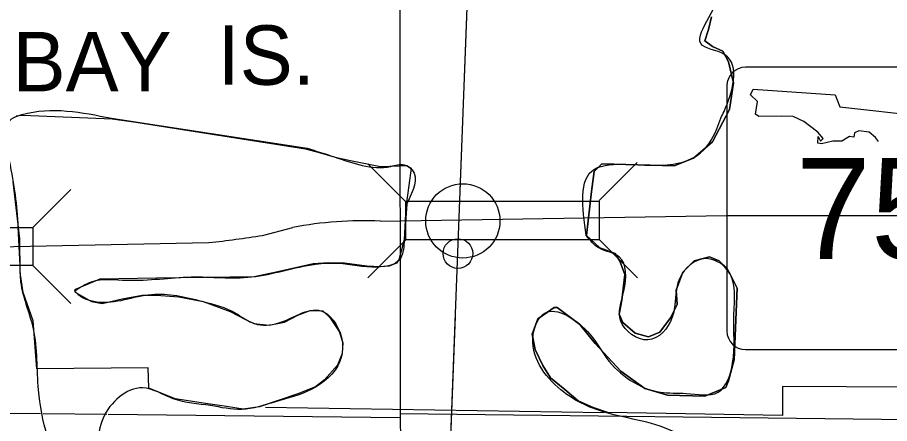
# Model space of a CAD drawing. Extents: x 408847 to 817539, y 923858 to 1151780.
# Drawn here: x 476052 to 481921, y 1078190 to 1080923 of the extents above; entities that cross this region are included whole.
import ezdxf

# ---------------------------------------------------------------- set-up
doc = ezdxf.new("R2010")
doc.units = 0
for name, color, linetype in [('Bridges', 7, 'Continuous'), ('Cities Incorporated Area', 7, 'Continuous'), ('Cities Incorporated Linear Boundaries', 7, 'Continuous'), ('Lakes and Ponds', 7, 'Continuous'), ('Level 12', 7, 'Continuous'), ('Level 39', 7, 'Continuous'), ('Narrow River Creek and Branch and Slough', 7, 'Continuous'), ('Roadshields State Highways', 7, 'Continuous'), ('Section Lines', 7, 'Continuous'), ('State Routes Highway Center Lines', 7, 'Continuous'), ('Township  and Range lines', 7, 'Continuous')]:
    doc.layers.add(name, color=color, linetype=linetype)

msp = doc.modelspace()

# ---------------------------------------------------------------- linework, layer by layer
at = {"layer": 'Bridges'}
for p, q in [((478409.7, 1079938), (478665.7, 1079682)), ((479966.8, 1079691.1), (480222.8, 1079947.1)), ((476155.3, 1079509.6), (476411.3, 1079765.6)), ((478665.7, 1079426), (478665.7, 1079687.3)), ((478665.7, 1079687.3), (479967.5, 1079687.3)), ((479967.5, 1079687.3), (479967.5, 1079426)), ((478665.7, 1079426), (478409.7, 1079170)), ((479967.5, 1079426), (478665.7, 1079426)), ((479969.8, 1079426), (480225.8, 1079170)), ((476155.3, 1079253.6), (476411.3, 1078997.6))]:
    msp.add_line(p, q, dxfattribs=at)
msp.add_lwpolyline([(475643.3, 1079509.6), (476155.3, 1079509.6), (476155.3, 1079253.6), (475643.3, 1079253.6)], close=True, dxfattribs=at)
msp.add_circle((479049.7, 1079554), 250, dxfattribs=at)
at = {"layer": 'Cities Incorporated Area'}
for p, q in [((486536.7, 1078406.2), (481199.8, 1078440.5)), ((481199.8, 1078440.5), (481201.8, 1078244.7)), ((481201.8, 1078244.7), (480026.3, 1078263.9))]:
    msp.add_line(p, q, dxfattribs=at)
for points in [[(480139.1, 1079193.4), (480107, 1079283.3), (480074.9, 1079334.6), (479972.3, 1079373.1), (479882.5, 1079456.6), (479914.6, 1079751.8), (479933.8, 1079886.6), (479985.2, 1079937.9), (480472.6, 1079925.1), (480600.9, 1079976.4), (480729.2, 1080085.5), (480844.6, 1080303.8), (480870.3, 1080483.5), (480838.2, 1080624.7), (480799.7, 1080695.3), (480729.2, 1080727.4), (480677.8, 1080765.9), (480703.5, 1080842.9), (480722.7, 1080926.3)], [(480722.7, 1080926.3), (480703.5, 1080842.9), (480677.8, 1080765.9), (480729.2, 1080727.4), (480799.7, 1080695.3), (480838.2, 1080624.7), (480870.3, 1080483.5), (480844.6, 1080303.8), (480729.2, 1080085.5), (480600.9, 1079976.4), (480472.6, 1079925.1), (479985.2, 1079937.9), (479933.8, 1079886.6), (479914.6, 1079751.8), (479882.5, 1079456.6), (479972.3, 1079373.1), (480074.9, 1079334.6), (480107, 1079283.3), (480139.1, 1079193.4)], [(476043.5, 1080261.4), (476087.1, 1080265.4), (476690.1, 1080241.5), (476848.8, 1080217.7), (477991.4, 1080039.1), (478082.6, 1080015.2), (478189.8, 1079983.5), (478292.9, 1079959.7), (478495.2, 1079920), (478622.2, 1079923.9), (478673.8, 1079927.9), (478701.5, 1079908.1), (478685.7, 1079792.9), (478665.8, 1079646), (478653.9, 1079427.7), (478618.2, 1079292.7), (478602.3, 1079268.9), (478554.7, 1079249), (478495.2, 1079245.1), (478404, 1079249), (478253.2, 1079268.9), (478146.1, 1079272.9), (478043, 1079264.9), (477793, 1079209.3), (477646.2, 1079177.6), (476987.7, 1079169.6), (476606.8, 1079161.7), (476436.2, 1079090.2), (476440.2, 1079074.4), (476551.3, 1079010.8), (476622.7, 1078998.9), (476757.6, 1079030.7), (476892.5, 1079054.5), (476987.7, 1079054.5), (477138.4, 1079042.6), (477301.1, 1079010.8), (477483.6, 1078943.4), (477590.7, 1078887.8), (477642.3, 1078864), (477745.4, 1078852), (477848.6, 1078871.9), (477939.8, 1078919.5), (478023.1, 1078952.1), (478106.4, 1078948.1), (478154, 1078904.4), (478217.5, 1078809.2), (478241.3, 1078733.7), (478237.4, 1078662.3), (478205.6, 1078584.1), (478118.3, 1078484.8), (478058.8, 1078437.2), (477939.8, 1078389.5), (477681.9, 1078302.2), (477570.8, 1078286.3), (477459.8, 1078306.2), (477332.8, 1078322), (477114.6, 1078357.8), (476936.1, 1078429.2), (476932.1, 1078564.2), (476182.3, 1078559.1)], [(476182.3, 1078559.1), (476158.5, 1078880.6), (476091.1, 1079071.2), (476071.3, 1079206.2), (476067.3, 1079432.4), (476023.7, 1079817.5)], [(480026.3, 1078263.9), (479927.4, 1078298), (479824.8, 1078343), (479735, 1078420), (479638.8, 1078497), (479587.5, 1078580.4), (479536.2, 1078689.5), (479516.9, 1078792.2), (479555.4, 1078894.9), (479619.5, 1078939.9), (479664.4, 1078972), (479683.7, 1078972), (479837.6, 1078856.4), (479940.2, 1078728.1), (480113.4, 1078541.9), (480273.7, 1078426.4), (480427.7, 1078381.5), (480677.8, 1078375.1), (480818.9, 1078432.8), (480838.2, 1078477.7), (480876.6, 1078618.9), (480895.9, 1079100.3), (480851, 1079190.2), (480825.3, 1079235.1), (480774, 1079286.4), (480709.9, 1079312.1), (480607.3, 1079286.4), (480530.3, 1079209.4), (480485.4, 1079087.5), (480491.8, 1078991.2), (480446.9, 1078901.3), (480376.4, 1078805.1), (480299.4, 1078773), (480209.6, 1078798.7), (480126.2, 1078869.3), (480100.6, 1078927), (480119.8, 1079020.1), (480139.1, 1079193.4)], [(480139.1, 1079193.4), (480119.8, 1079020.1), (480100.6, 1078927), (480126.2, 1078869.3), (480209.6, 1078798.7), (480299.4, 1078773), (480376.4, 1078805.1), (480446.9, 1078901.3), (480491.8, 1078991.2), (480485.4, 1079087.5), (480530.3, 1079209.4), (480607.3, 1079286.4), (480709.9, 1079312.1), (480774, 1079286.4), (480825.3, 1079235.1), (480851, 1079190.2), (480895.9, 1079100.3), (480876.6, 1078618.9), (480838.2, 1078477.7), (480818.9, 1078432.8), (480677.8, 1078375.1), (480427.7, 1078381.5), (480273.7, 1078426.4), (480113.4, 1078541.9), (479940.2, 1078728.1), (479837.6, 1078856.4), (479683.7, 1078972), (479664.4, 1078972), (479619.5, 1078939.9), (479555.4, 1078894.9), (479516.9, 1078792.2), (479536.2, 1078689.5), (479587.5, 1078580.4), (479638.8, 1078497), (479735, 1078420), (479824.8, 1078343), (479927.4, 1078298), (480026.3, 1078263.9)]]:
    msp.add_lwpolyline(points, dxfattribs=at)
at = {"layer": 'Cities Incorporated Linear Boundaries'}
msp.add_line((477721.3, 1078301.7), (480001, 1078264.3), dxfattribs=at)
at = {"layer": 'Lakes and Ponds'}
for p, q in [((476684.8, 1080244.5), (478001.1, 1080043.3)), ((478672, 1079670), (478654.8, 1079411.7)), ((476070.6, 1079254.8), (476057.8, 1079512.2))]:
    msp.add_line(p, q, dxfattribs=at)
for points in [[(480785.3, 1080245.6), (480807.4, 1080291.1), (480811.4, 1080673.5), (480651.2, 1080747.6), (480705.2, 1080921.8), (480807.4, 1081146), (480855.4, 1081304.2), (480891.4, 1081440.3), (480993.6, 1081770.7), (481053.6, 1082073), (481159.7, 1082455.5), (481233.8, 1082639.7), (481057.6, 1083090.2), (480977.5, 1083344.4), (480999.8, 1083639.4), (480955.5, 1083947.1), (480913.5, 1084253.4), (480781.3, 1084409.6), (480483, 1084589.8), (480084.6, 1084699.9), (479758.2, 1084571.8), (479471.9, 1084525.7), (479279.7, 1084665.9), (479273.7, 1084928.2), (479425.9, 1085144.4), (479501.9, 1085392.7), (479642.1, 1085709)], [(476057.8, 1079512.2), (476056.5, 1079538.6), (475993.1, 1079991.7), (476012.6, 1080240.1), (476080.8, 1080269.4), (476684.8, 1080244.5)], [(479880.4, 1079454.9), (479935.7, 1079902.5), (480151.9, 1079934.5), (480464.2, 1079936.5), (480626.4, 1079994.6), (480758.6, 1080172.8), (480785.3, 1080245.6)], [(478001.1, 1080043.3), (478184.5, 1079985), (478564.9, 1079921), (478654.4, 1079931.5), (478708.8, 1079898.3), (478672, 1079670)], [(480802.1, 1077173.4), (480485, 1078124.7), (480002.5, 1078266.8), (479710.1, 1078417), (479523.9, 1078791.4), (479598, 1078931.6), (479904.4, 1078791.4), (480018.5, 1078629.2), (480378.9, 1078401), (480553.1, 1078393), (480767.3, 1078401), (480865.4, 1078597.2), (480873.4, 1078911.6), (480829.4, 1079225.9), (480683.2, 1079300), (480509, 1079169.8), (480459, 1078905.6), (480294.8, 1078753.4), (480112.6, 1078879.5), (480132.6, 1079081.7), (480102.6, 1079312), (479968.4, 1079370.1), (479880.4, 1079454.9)], [(478654.8, 1079411.7), (478623.7, 1079292.9), (478473.6, 1079242.8), (478209.3, 1079266.9), (478059.1, 1079260.8), (477626.7, 1079174.7), (477222.2, 1079174.7), (476789.7, 1079152.7), (476549.2, 1079142.2), (476439, 1079082)], [(477806, 1071359.2), (477681.9, 1071311.2), (477651.9, 1071599.5), (477433.6, 1071891.8), (477275.4, 1072156.1), (476829, 1072594.6), (476760.9, 1072644.6), (476710.8, 1072762.8), (476748.9, 1072957), (476835, 1073045.1), (477059.2, 1072880.9), (477245.4, 1072702.7), (477425.6, 1072628.6), (477511.7, 1072756.8), (477405.6, 1072858.9), (477197.4, 1072949), (477175.3, 1073025.1), (477223.4, 1073101.1), (477165.3, 1073255.3), (477037.2, 1073397.5), (476945.1, 1073477.6), (476470.6, 1073551.6), (476206.3, 1073415.5), (476013.2, 1073211.5), (475935.7, 1073223.7), (475935.7, 1073274.7), (476030.1, 1073371.4), (476166.2, 1073501.6), (476298.4, 1073641.7), (476472.6, 1073749.8), (476800.9, 1073705.8), (476969.1, 1073723.8), (476903, 1073854), (476750.9, 1073952.1), (476602.7, 1074054.2), (476418.5, 1074154.3), (476350.4, 1074456.6), (476236.3, 1074586.8), (476050.1, 1074765), (476044.1, 1074881.1), (476006.1, 1075027.2), (475918, 1075299.5), (475859.9, 1075541.8), (475873.9, 1075844.1), (475755.8, 1075682), (475755.8, 1075487.8), (475737.8, 1075207.4), (475711.7, 1075007.2), (475671.7, 1074765), (475689.7, 1074618.8), (475709.7, 1074564.7), (475713.7, 1074440.6), (475437.4, 1074534.7), (475265.2, 1074648.8), (475107.1, 1074855), (474854.8, 1075255.5), (474838.5, 1075446.2), (474950.5, 1075606.9), (475047, 1075577.8), (475169.1, 1075477.7), (475481.5, 1075637.9), (475599.6, 1075810.1), (475607.6, 1076028.3), (475485.5, 1076210.5), (475195.2, 1076168.5), (474978.9, 1076156.5), (475011, 1076334.7), (475165.1, 1076552.9), (475229.2, 1076891.3), (475237.2, 1077169.6), (475233.2, 1077445.9), (475255.2, 1077730.2), (475207.2, 1077990.5), (475267.2, 1078052.6), (475335.4, 1078057.5), (475503.5, 1078014.5), (475643.7, 1077758.2), (475657.7, 1077425.9), (475619.6, 1077101.5), (475561.6, 1076781.2), (475601.6, 1076356.7), (475791.8, 1076064.4), (476020.1, 1076042.4), (476326.4, 1076374.7), (476410.5, 1076627), (476244.3, 1076941.4), (475964, 1077123.6), (475956, 1077335.8), (476006.1, 1077522), (475960, 1077872.4), (475906, 1078098.6), (475873.9, 1078364.9), (475891.9, 1078721.3), (475885.9, 1078919.5), (475871.9, 1079113.7), (475807.4, 1079249.7)], [(476439, 1079082), (476444.5, 1079075.6), (476586.7, 1079009.6), (476955.1, 1079059.7), (477293.5, 1079013.6), (477523.7, 1078931.6), (477629.9, 1078869.5), (477790, 1078861.5), (478094.4, 1078949.6), (478230.5, 1078779.4), (478222.5, 1078609.2), (478028.3, 1078419), (477788, 1078336.9), (477561.8, 1078284.8), (477351.6, 1078310.9), (477101.3, 1078356.9), (476893, 1078431), (476628.8, 1078226.8), (476590.7, 1078050.6), (476538.7, 1077702.2), (476496.6, 1077435.9), (476424.5, 1077277.7), (476270.4, 1077211.7), (476276.4, 1077263.7), (476296.4, 1077544), (476310.4, 1077846.4), (476252.3, 1078104.6), (476194.3, 1078417), (476160.2, 1078827.4), (476076.2, 1079143.8), (476070.6, 1079254.8)]]:
    msp.add_spline(points, degree=3, dxfattribs=at)
at = {"layer": 'Level 12'}
msp.add_circle((479016.5, 1079334.4), 99.8, dxfattribs=at)
at = {"layer": 'Narrow River Creek and Branch and Slough'}
for points in [[(482087, 1064025.6), (481376.6, 1064839.5), (481078, 1065344.3), (480727.9, 1066175.2), (479832.2, 1068355.9), (479718.9, 1068644.4), (479430.6, 1070218.6), (478864.3, 1073376.6), (478812.9, 1073644.4), (478802.6, 1073809.3), (478864.3, 1075340), (479090.9, 1081286.4), (479132, 1082007.6), (479121.8, 1082275.4), (478754.2, 1083480.8), (478640.9, 1083686.8), (478424.7, 1083934.1), (478260, 1084078.3), (478064.4, 1084346.2)], [(479066, 1080633.4), (479090.9, 1081286.4), (479103.5, 1081507.6)], [(479032.7, 1079759), (479066, 1080633.4)], [(478967, 1078035.3), (479000.3, 1078909.7)]]:
    msp.add_lwpolyline(points, dxfattribs=at)
at = {"layer": 'Roadshields State Highways'}
for p, q in [((482601.8, 1080588.3), (480951.8, 1080588.3)), ((480826.8, 1080463.3), (480826.8, 1078813.3)), ((480951.8, 1078688.3), (482601.8, 1078688.3))]:
    msp.add_line(p, q, dxfattribs=at)
for points in [[(481846.4, 1080089.2), (481826.7, 1080114.5), (481783.9, 1080150.8), (481714.7, 1080160.7), (481685, 1080147.5), (481681.7, 1080117.8), (481652, 1080121.1), (481599.3, 1080091.4), (481539.9, 1080091.4), (481464.1, 1080071.6), (481437.8, 1080078.2), (481441, 1080121.1), (481457.5, 1080091.4), (481474, 1080107.9), (481437.8, 1080150.8), (481381.7, 1080193.7), (481345.5, 1080223.4), (481272.9, 1080256.3), (481197.1, 1080259.6), (481042.2, 1080256.3), (481019.1, 1080272.8), (481032.3, 1080358.6), (480986.1, 1080401.5), (481002.6, 1080441.1)], [(481002.6, 1080441.1), (481556.4, 1080401.5), (481586.1, 1080322.3), (482149.8, 1080259.6)]]:
    msp.add_lwpolyline(points, dxfattribs=at)
for centre, start, end in [((480951.8, 1080463.3), 90, 180), ((480951.8, 1078813.3), 180, 270)]:
    msp.add_arc(centre, 125, start, end, dxfattribs=at)
at = {"layer": 'Section Lines'}
for p, q in [((475889.1, 1078261.2), (476206.7, 1078257.6)), ((476226.3, 1078257.4), (476653.6, 1078252.7)), ((476663.5, 1078252.6), (478628.6, 1078230.8))]:
    msp.add_line(p, q, dxfattribs=at)
at = {"layer": 'State Routes Highway Center Lines'}
for p, q in [((478494.9, 1079552.9), (480825.1, 1079591.4)), ((477702.5, 1079456.5), (477904.7, 1079509.5)), ((475639, 1079374.6), (477341.4, 1079408.3))]:
    msp.add_line(p, q, dxfattribs=at)
msp.add_lwpolyline([(480825.1, 1079591.4), (482867.6, 1079590.4), (482831, 1078212.5), (483765, 1078193.3)], dxfattribs=at)
for centre, radius, start, end in [((478381.7, 1077055.3), 2500.1, 87.4037, 100.99889), ((476566.9, 1086590), 7223.3, 276.15483, 279.04463)]:
    msp.add_arc(centre, radius, start, end, dxfattribs=at)
at = {"layer": 'Township  and Range lines'}
for p, q in [((478620.3, 1084241.6), (478628.6, 1078230.8)), ((483840, 1078193.1), (478628.6, 1078255)), ((478628.6, 1078255), (478667.2, 1072852.3))]:
    msp.add_line(p, q, dxfattribs=at)

# ---------------------------------------------------------------- texts
at = {"layer": 'Level 39'}
for s, rotation, p in [('IS.', 0.00055, (477399.6, 1080469.8)), ('BAY', 0.00056, (476019.8, 1080426))]:
    msp.add_text(s, height=400, rotation=rotation, dxfattribs=at).set_placement(p)
at = {"layer": 'Roadshields State Highways'}
msp.add_text('758', height=680, dxfattribs=at).set_placement((481290, 1079298.3))

doc.saveas('drawing.dxf')
